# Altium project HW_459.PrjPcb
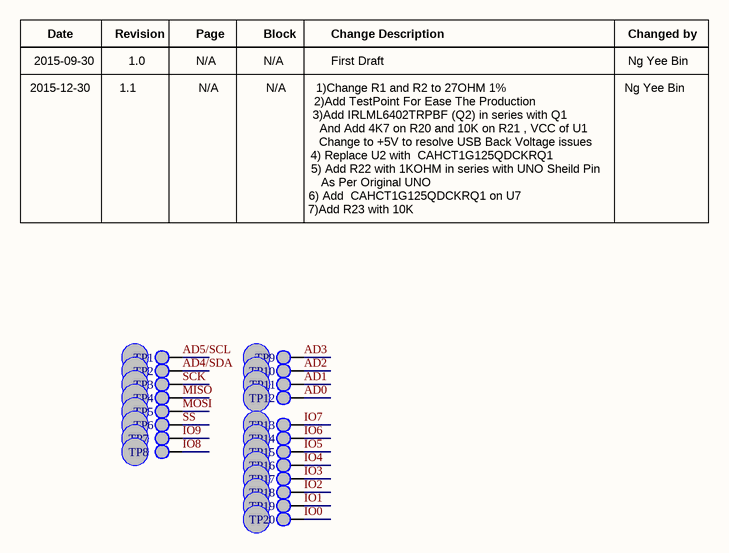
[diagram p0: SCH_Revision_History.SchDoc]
2 sheets, 108 parts. Net scope: global (net labels, ports and power ports of the same name join across sheets).
Board file: NERO.PcbDoc
Sheets:
  SCH_Revision_History.SchDoc
  nero.SchDoc

## Sheet SCH_Revision_History.SchDoc: FTDI Nero Schematic
size A4; CompanyName: Future Technology Devices International Ltd.; Organization: Future Technology Devices International Ltd.; Address1: 178 Paya Lebar Road,; Address2: #07-04/05; Address3: Singapore 409030; Address4: http://www.ftdichip.com; DocumentNumber: HW_459; Revision: 1.1; SheetNumber: 1; SheetTotal: 2; Title2: Revision History

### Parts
TP1  SMT_TP  [TP_SMT_1MM]  (value not drawn)  (no BOM)
TP2  SMT_TP  [TP_SMT_1MM]  (value not drawn)  (no BOM)
TP3  SMT_TP  [TP_SMT_1MM]  (value not drawn)  (no BOM)
TP4  SMT_TP  [TP_SMT_1MM]  (value not drawn)  (no BOM)
TP5  SMT_TP  [TP_SMT_1MM]  (value not drawn)  (no BOM)
TP6  SMT_TP  [TP_SMT_1MM]  (value not drawn)  (no BOM)
TP7  SMT_TP  [TP_SMT_1MM]  (value not drawn)  (no BOM)
TP8  SMT_TP  [TP_SMT_1MM]  (value not drawn)  (no BOM)
TP9  SMT_TP  [TP_SMT_1MM]  (value not drawn)  (no BOM)
TP10  SMT_TP  [TP_SMT_1MM]  (value not drawn)  (no BOM)
TP11  SMT_TP  [TP_SMT_1MM]  (value not drawn)  (no BOM)
TP12  SMT_TP  [TP_SMT_1MM]  (value not drawn)  (no BOM)
TP13  SMT_TP  [TP_SMT_1MM]  (value not drawn)  (no BOM)
TP14  SMT_TP  [TP_SMT_1MM]  (value not drawn)  (no BOM)
TP15  SMT_TP  [TP_SMT_1MM]  (value not drawn)  (no BOM)
TP16  SMT_TP  [TP_SMT_1MM]  (value not drawn)  (no BOM)
TP17  SMT_TP  [TP_SMT_1MM]  (value not drawn)  (no BOM)
TP18  SMT_TP  [TP_SMT_1MM]  (value not drawn)  (no BOM)
TP19  SMT_TP  [TP_SMT_1MM]  (value not drawn)  (no BOM)
TP20  SMT_TP  [TP_SMT_1MM]  (value not drawn)  (no BOM)

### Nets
AD0: TP12.TP
AD1: TP11.TP
AD2: TP10.TP
AD3: TP9.TP
AD4/SDA: TP2.TP
AD5/SCL: TP1.TP
IO0: TP20.TP
IO1: TP19.TP
IO2: TP18.TP
IO3: TP17.TP
IO4: TP16.TP
IO5: TP15.TP
IO6: TP14.TP
IO7: TP13.TP
IO8: TP8.TP
IO9: TP7.TP
MISO: TP4.TP
MOSI: TP5.TP
SCK: TP3.TP
SS: TP6.TP

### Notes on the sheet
- 2015-09-30
- Date
- Revision
- 1.0
- Page
- N/A
- Block
- Change Description
- First Draft
- Changed by
- Ng Yee Bin
- 2015-12-30
- 1.1
- 1)Change R1 and R2 to 27OHM 1%
- 2)Add TestPoint For Ease The Production
- 3)Add IRLML6402TRPBF (Q2) in series with Q1
- And Add 4K7 on R20 and 10K on R21 , VCC of U1
- As Per Original UNO
- 6) Add  CAHCT1G125QDCKRQ1 on U7
- 4) Replace U2 with  CAHCT1G125QDCKRQ1
- Change to +5V to resolve USB Back Voltage issues
- 5) Add R22 with 1KOHM in series with UNO Sheild Pin
- 7)Add R23 with 10K

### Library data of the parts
TP1-TP20 = TP_SMT_1mm

## Sheet nero.SchDoc: FTDI Nero Schematic
size A4; CompanyName: Future Technology Devices International Ltd.; Organization: Future Technology Devices International Ltd.; Address1: 178 Paya Lebar Road,; Address2: #07-04/05; Address3: Singapore 409030; Address4: http://www.ftdichip.com; DocumentNumber: HW_459; Revision: 1.1; SheetNumber: 2; SheetTotal: 2; Title2: Inspired by Arduino UNO R3
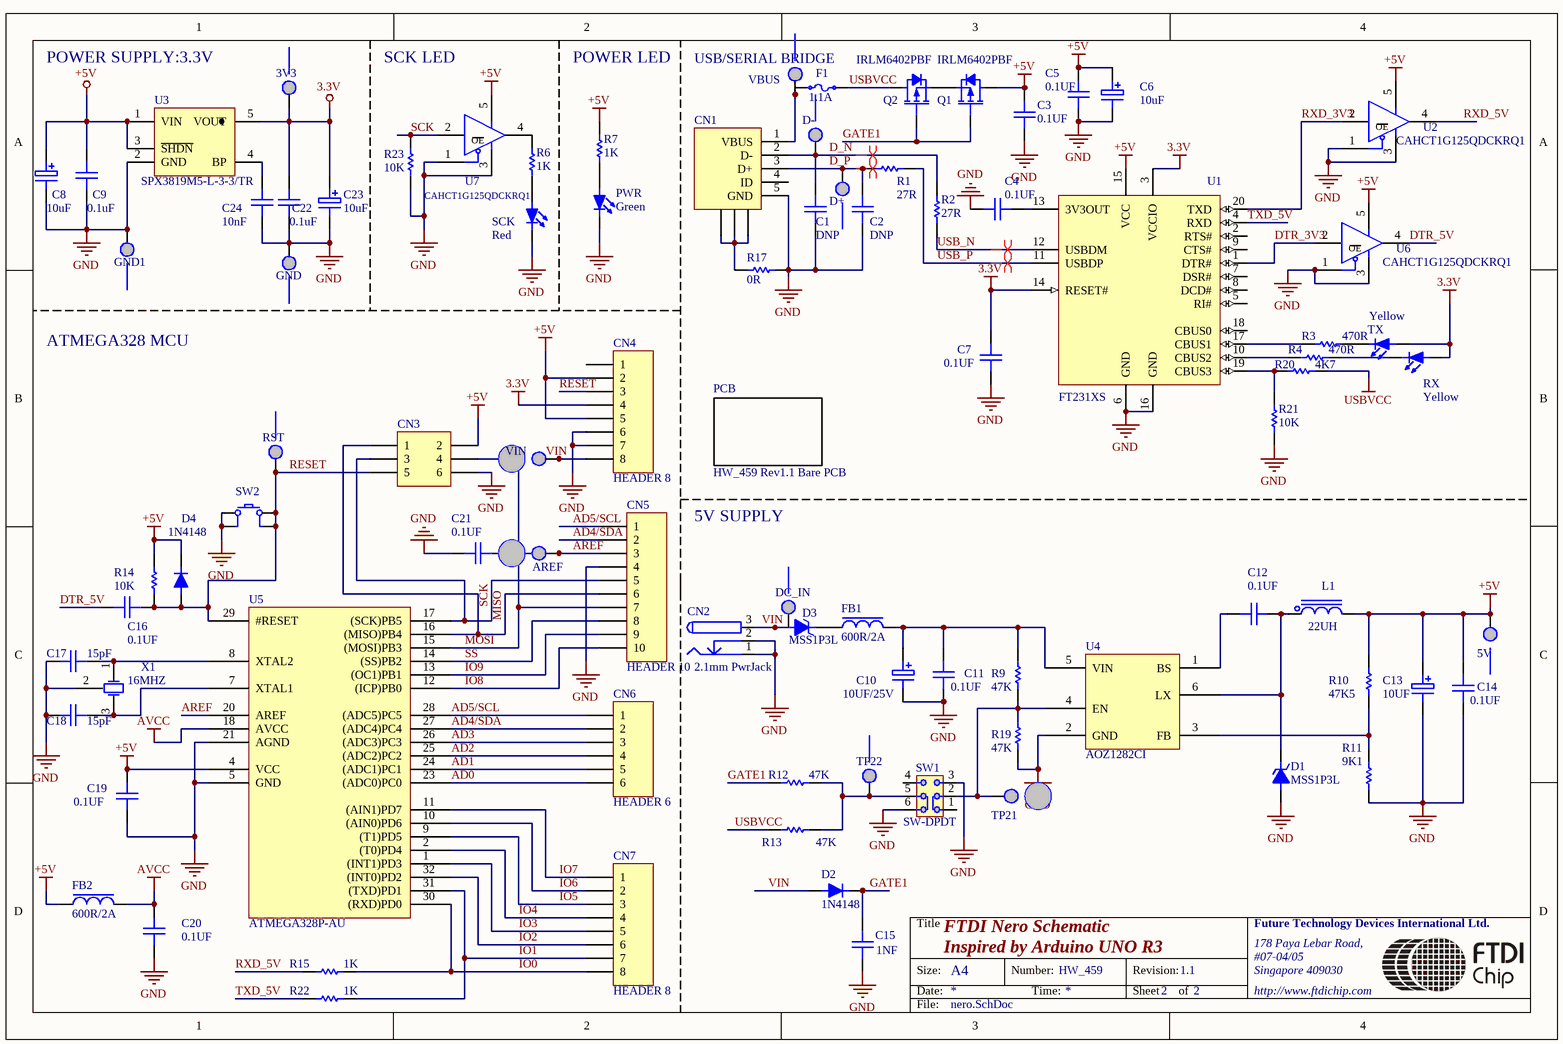
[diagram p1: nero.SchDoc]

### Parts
3V3  SMT_TP  [TP_SMT_1MM]  (value not drawn)  (no BOM)
5V  SMT_TP  [TP_SMT_1MM]  (value not drawn)  (no BOM)
AREF  SMT_TP  [TP_SMT_1MM]  (value not drawn)  (no BOM)
C1  DNP  [CAPC1608-0603]  (no BOM)
C2  DNP  [CAPC1608-0603]  (no BOM)
C3  0.1UF  [CAPC1608-0603]
C4  0.1UF  [CAPC1608-0603]
C5  0.1UF  [CAPC1608-0603]
C6  10uF  [CAPM-A-3216-18]
C7  0.1UF  [CAPC1608-0603]
C8  10uF  [CAPM-A-3216-18]
C9  0.1uF  [CAPC1608-0603]
C10  10UF/25V  [CAPM-B-3528-21]
C11  0.1UF  [CAPC1608-0603]
C12  0.1UF  [CAPC1608-0603]
C13  10UF  [CAPM-A-3216-18]
C14  0.1UF  [CAPC1608-0603]
C15  1NF  [CAPC1608-0603]
C16  0.1UF  [CAPC1608-0603]
C17  15pF  [CAPC1608-0603]
C18  15pF  [CAPC1608-0603]
C19  0.1UF  [CAPC1608-0603]
C20  0.1UF  [CAPC1608-0603]
C21  0.1UF  [CAPC1608-0603]
C22  0.1uF  [CAPC1608-0603]
C23  10uF  [CAPM-A-3216-18]
C24  10nF  [CAPC1608-0603]
CN1  CN USB  [CN_USB_MICRO_HOUSING]  (value not drawn)
CN2  2.1mm PwrJack  [CN_2.1mm Power Socket routed pins]
CN3  TC2030-IDC-FP  [CN_HDR2X3]  (value not drawn)
CN4  HEADER 8  [CN_HDR1X8]
CN5  HEADER 10  [CN_HDR1X10]
CN6  HEADER 6  [HDR1X6]
CN7  HEADER 8  [CN_HDR1X8]
D1  MSS1P3L  [DIODE_MSS1P3L]
D2  1N4148  [SOD-323]
D3  MSS1P3L  [DIODE_MSS1P3L]
D4  1N4148  [SOD-323]
D+  SMT_TP  [TP_SMT_1MM]  (value not drawn)  (no BOM)
D-  SMT_TP  [TP_SMT_1MM]  (value not drawn)  (no BOM)
DC_IN  SMT_TP  [TP_SMT_1MM]  (value not drawn)  (no BOM)
F1  1.1A  [Fuse_0ZCG Series]
FB1  600R/2A  [IND_C2012-0805]
FB2  600R/2A  [IND_C2012-0805]
GND  SMT_TP  [TP_SMT_1MM]  (value not drawn)  (no BOM)
GND1  SMT_TP  [TP_SMT_1MM]  (value not drawn)  (no BOM)
L1  22UH  [IND_NR6020]
PCB  HW_459 Rev1.1 Bare PCB
PWR  Green  [LEDC2012-0805]
Q1  IRLM6402PBF  [SOT23-3AL]
Q2  IRLM6402PBF  [SOT23-3AL]
R1  27R  [RESC1608-0603]
R2  27R  [RESC1608-0603]
R3  470R  [RESC1608-0603]
R4  470R  [RESC1608-0603]
R6  1K  [RESC1608-0603]
R7  1K  [RESC1608-0603]
R9  47K  [RESC1608-0603]
R10  47K5  [RESC1608-0603]
R11  9K1  [RESC1608-0603]
R12  47K  [RESC1608-0603]
R13  47K  [RESC1608-0603]
R14  10K  [RESC1608-0603]
R15  1K  [RESC1608-0603]
R17  0R  [RESC1608-0603]
R19  47K  [RESC1608-0603]
R20  4K7  [RESC1608-0603]
R21  10K  [RESC1608-0603]
R22  1K  [RESC1608-0603]
R23  10K  [RESC1608-0603]
RST  SMT_TP  [TP_SMT_1MM]  (value not drawn)  (no BOM)
RX  Yellow  [LEDC2012-0805]
SCK  Red  [LEDC2012-0805]
SW1  SW-DPDT  [SW_JS202011AQN]
SW2  SW_PB  [SW_PushButton]  (value not drawn)
TP21  SMT_TP  [TP_SMT_1MM]  (value not drawn)  (no BOM)
TP22  SMT_TP  [TP_SMT_1MM]  (value not drawn)  (no BOM)
TX  Yellow  [LEDC2012-0805]
U1  FT231XS  [SSOP20]
U2  CAHCT1G125QDCKRQ1  [SC70-5]
U3  SPX3819M5-L-3-3/TR  [SOT23-5AL]
U4  AOZ1282CI  [SOT23-6N]
U5  ATMEGA328P-AU  [TQFP80P900X900X160-32N]
U6  CAHCT1G125QDCKRQ1  [SC70-5]
U7  CAHCT1G125QDCKRQ1  [SC70-5]
VBUS  SMT_TP  [TP_SMT_1MM]  (value not drawn)  (no BOM)
VIN  SMT_TP  [TP_SMT_1MM]  (value not drawn)  (no BOM)
X1  16MHZ  [CRYSTAL_16MHZ]

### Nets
3.3V: 3V3.TP C7.1 C22.1 C23.1 CN4.4 RX.2(A) TX.2(A) U1.3(VCCIO) U1.14(RESET#) U3.5(VOUT)
+5V: 5V.TP C3.1 C5.1 C6.1 C8.1 C9.1 C13.1 C14.1 C19.1 CN3.2 CN4.2 CN4.5 D4.1(K) FB2.2 L1.2 Q1.3(D) R7.1 R10.2 R14.2 U1.15(VCC) U2.5(VCC) U3.1(VIN) U3.3(~{SHDN}) U5.4(VCC) U6.5(VCC) U7.5(VCC)
AVCC: C20.1 FB2.1 U5.18(AVCC)
GND: C1.2 C2.2 C3.2 C4.1 C5.2 C6.2 C7.2 C8.2 C9.2 C10.2 C11.2 C13.2 C14.2 C15.2 C17.1 C18.1 C19.2 C20.2 C21.1 C22.2 C23.2 C24.2 CN1.5(GND) CN2.1 CN2.2 CN3.6 CN4.6 CN4.7 CN5.4 D1.2(A) GND.TP GND1.TP PWR.1(K) R11.1 R17.2 R19.2 R21.1 R23.2 SCK.1(K) SW1.3 SW1.6 SW2.1 SW2.2 U1.6(GND) U1.16(GND) U2.1(~{OE}) U2.3(GND) U3.2(GND) U4.2(GND) U5.5(GND) U5.21(AGND) U6.1(~{OE}) U6.3(GND) U7.1(~{OE}) U7.3(GND) X1.2(GND)
USBVCC: F1.2 Q2.3(D) R13.1 R20.1
AD0: CN6.6 U5.23((ADC0)PC0)
AD1: CN6.5 U5.24((ADC1)PC1)
AD2: CN6.4 U5.25((ADC2)PC2)
AD3: CN6.3 U5.26((ADC3)PC3)
AD4/SDA: CN5.2 CN6.2 U5.27((ADC4)PC4)
AD5/SCL: CN5.1 CN6.1 U5.28((ADC5)PC5)
AREF: AREF.TP C21.2 CN5.3 U5.20(AREF)
D_N: C1.1 CN1.2(D-) D-.TP R2.2
D_P: C2.1 CN1.3(D+) D+.TP R1.1
DTR_3V3: U1.1(DTR#) U6.2(A)
DTR_5V: C16.1 U6.4(Y)
GATE1: C15.1 D2.1(K) Q1.1(G) Q2.1(G) R12.1
IO0: CN7.8 R15.2 U5.30((RXD)PD0)
IO1: CN7.7 R22.2 U5.31((TXD)PD1)
IO2: CN7.6 U5.32((INT0)PD2)
IO3: CN7.5 U5.1((INT1)PD3)
IO4: CN7.4 U5.2((T0)PD4)
IO5: CN7.3 U5.9((T1)PD5)
IO6: CN7.2 U5.10((AIN0)PD6)
IO7: CN7.1 U5.11((AIN1)PD7)
IO8: CN5.10 U5.12((ICP)PB0)
IO9: CN5.9 U5.13((OC1)PB1)
MISO: CN3.1 CN5.6 U5.16((MISO)PB4)
MOSI: CN3.4 CN5.7 U5.15((MOSI)PB3)
RESET: C16.2 CN3.5 CN4.3 D4.2(A) R14.1 RST.TP SW2.3 SW2.4 U5.29(#RESET)
RXD_3V3: U1.20(TXD) U2.2(A)
RXD_5V: R15.1 U2.4(Y)
SCK: CN3.3 CN5.5 R23.1 U5.17((SCK)PB5) U7.2(A)
SS: CN5.8 U5.14((SS)PB2)
TXD_5V: R22.1 U1.4(RXD)
USB_N: R2.1 U1.12(USBDM)
USB_P: R1.2 U1.11(USBDP)
VIN: CN2.3 CN4.8 D2.2(A) D3.2(A) DC_IN.TP VIN.TP
NetC4_2: C4.2 U1.13(3V3OUT)
NetC10_1: C10.1 C11.1 FB1.1 R9.1 U4.5(VIN)
NetC12_1: C12.1 U4.1(BS)
NetC12_2: C12.2 D1.1(K) L1.1 U4.6(LX)
NetC17_2: C17.2 U5.8(XTAL2) X1.1(OSC1)
NetC18_2: C18.2 U5.7(XTAL1) X1.3(OSC2)
NetC24_1: C24.1 U3.4(BP)
NetCN1_1: CN1.1(VBUS) F1.1 VBUS.TP
NetCN1_6: CN1.6(SHLD) CN1.7(SHLD) CN1.8(SHLD) R17.1
NetD3_1: D3.1(K) FB1.2
NetPWR_2: PWR.2(A) R7.2
NetQ1_2: Q1.2(S) Q2.2(S)
NetR3_1: R3.1 U1.17(CBUS1)
NetR3_2: R3.2 TX.1(K)
NetR4_1: R4.1 U1.10(CBUS2)
NetR4_2: R4.2 RX.1(K)
NetR6_1: R6.1 U7.4(Y)
NetR6_2: R6.2 SCK.2(A)
NetR9_2: R9.2 R19.1 SW1.2 TP21.TP U4.4(EN)
NetR10_1: R10.1 R11.2 U4.3(FB)
NetR12_2: R12.2 R13.2 SW1.5 TP22.TP
NetR20_2: R20.2 R21.2 U1.19(CBUS3)

Not connected (* = marked no-connect by the designer): CN1 4(ID); CN4 1; SW1 1 4; U1 2(RTS#) 5(RI#) 7(DSR#) 8(DCD#) 9(CTS#) 18(CBUS0)

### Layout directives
differential pair: D_N, D_P, USB_N, USB_P

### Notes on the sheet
- POWER SUPPLY:3.3V
- SCK LED
- POWER LED
- USB/SERIAL BRIDGE
- ATMEGA328 MCU
- 5V SUPPLY

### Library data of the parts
3V3 5V AREF D+ D- DC_IN GND GND1 RST TP21 TP22 VBUS VIN = TP_SMT_1mm
C1 C2 = CAP_SEMI: Capacitor bipolar
C3-C5 C7 C9 C11 C12 C14 C16 C19 C20 = CAP_SEMI: Capacitor bipolar; Manufacturer: Samsung Electro-Mechanics America, Inc.; ManufacturerPartNo: CL10B104KB8SFNC; Note: CAP CERAMIC .1UF 50V X7R 0603
C6 C8 C13 C23 = CAP_POL: Polarized Capacitor; Manufacturer: AVX Corporation; ManufacturerPartNo: TAJA106M010RNJ; Note: CAP TANT LOESR 10.0UF 10V 20% SMD 1206
C10 = CAP_POL: Polarized Capacitor; Manufacturer: AVX Corporation; ManufacturerPartNo: TAJB106M025RNJ; Note: CAP TANT 10UF 25V 20% 1210
C15 = CAP_SEMI: Capacitor bipolar; Manufacturer: Samsung Electro-Mechanics America, Inc.; ManufacturerPartNo: CL10B102KB8SFNC; Note: CAP 1000PF 50V CERAMIC X7R 0603
C17 C18 = CAP_SEMI: Capacitor bipolar; Manufacturer: Samsung Electro-Mechanics America, Inc.; ManufacturerPartNo: CL10C150JB8NNNC; Note: CAP CER 15PF 50V 5% NPO 0603
C21 C22 = CAP_SEMI: Capacitor bipolar; ManufacturerPartNo: CL10B104KB8SFNC; Manufacturer: Samsung Electro-Mechanics America, Inc.; Note: CAP CERAMIC .1UF 50V X7R 0603
C24 = CAP_SEMI: Capacitor bipolar; Manufacturer: Samsung Electro-Mechanics America, Inc.; ManufacturerPartNo: CL10B103MB8NCNC; Note: CAP CER 10000PF 50V X7R 0603
CN1 = CN_USB_MINI_B: Mini USB connector; SMD; Manufacturer: E-CONN ELECTRONIC(SU-ZHOU) CO., LTD; ManufacturerPartNo: MIC5-5BF1-KNM1-23; Note: MICRO USB B REC. (HOUSEING HOLE)
CN2 = CN_Power Jack: Low Voltage Power Supply Connector; Manufacturer: CUI Inc; ManufacturerPartNo: PJ-002A; Note: CONN POWER JACK 2.1MM
CN3 = CN_HEADER 2x3: ISP Connector, 6-Pin, Dual row, pitch 0.05"; Tag-Connect; TC2030-IDC-FP; Manufacturer: Sullins Connector Solutions; ManufacturerPartNo: PBC03DAAN; Note: CONN HEADER .100 DUAL STR 6POS
CN4 CN7 = CN_HEADER 8: Header, 8-Pin; Manufacturer: JunJia Electronics Technology; ManufacturerPartNo: FAS1851-0801A03XABXA; Note: Connector Receptacle 8 Position 0.100" (2.54mm) Tin Through Hole
CN5 = CN_HEADER 10: Header, 10-Pin; Manufacturer: JunJia Electronics Technology; ManufacturerPartNo: FAS1851-1001A03XABXA; Note: Connector Receptacle 10 Position 0.100" (2.54mm) Tin Through Hole
CN6 = CN_HEADER 6: Header, 6-Pin; Manufacturer: JunJia Electronics Technology; ManufacturerPartNo: FAS1851-0601A03XABXA; Note: Connector Receptacle 6 Position 0.100" (2.54mm) Tin Through Hole
D1 D3 = D_ZENER: Zener Diode; Manufacturer: VISHAY SEMICONDUCTOR; Note: DIODE SCHOTTKY 30V 1A MICROSMP
D2 D4 = D_UNI: DIODE SWITCH 75V 200MW SOD323; Manufacturer: Diodes Inc; ManufacturerPartNo: 1N4148WS-7-F
F1 = FUSE 2: Fuse; Manufacturer: Bel Fuse Inc; ManufacturerPartNo: 0ZCG0110AF2C; Note: PTC RESTTBLE 1.10A 16V CHIP 1812
FB1 FB2 = FERRITE_BEAD: Chip Ferrite Bead 0805; Manufacturer: TDK Corporation; ManufacturerPartNo: MPZ2012S601A; Note: FERRITE CHIP 600 OHM 2A 0805
L1 = IND_POWER: Magnetic-Core Inductor; Manufacturer: TAIYO YUDEN; ManufacturerPartNo: NR6028T220M; Note: IND 22UH 1.4A +-20% 6X6X2.8MM
PCB = PCB
PWR = D_LED: Typical LED diode; Manufacturer: Lite-On Inc; ManufacturerPartNo: LTST-C170GKT; Note: LED GREEN CLEAR 0805 SMD
Q1 Q2 = T_MOSFET-P: P-Channel MOSFET; SOT-23; Manufacturer: International Rectifier; ManufacturerPartNo: IRLML6402TRPBF; Note: MOSFET P-CH 20V 3.7A SOT-23
R1 R2 = RES1: Resistor; Manufacturer: UniOhm; ManufacturerPartNo: 0603WGF0270; Note: RES 27R OHM 1/16W 1% 0603 SMD
R3 R4 = RES1: Resistor; Manufacturer: UniOhm; ManufacturerPartNo: 0603WGJ0471; Note: RES 470 OHM 5% 1/16W 0603 SMD
R6 R7 R15 R22 = RES1: Resistor; Manufacturer: UniOhm; ManufacturerPartNo: 0603WGJ0102; Note: RES 1K OHM 1/16W 5% 0603 SMD
R9 R12 R13 R19 = RES1: Resistor; Manufacturer: UniOhm; ManufacturerPartNo: 0603WGJ0473; Note: RES 47K OHM 1/16W 5% 0603 SMD
R10 = RES1: Resistor; Manufacturer: UniOhm; ManufacturerPartNo: 0603WGF4752; Note: RES 47K5 OHM 1/16W 1% 0603 SMD
R11 = RES1: Resistor; Manufacturer: UniOhm; ManufacturerPartNo: 0603WGF0912; Note: RES 9K1 OHM 1% 1/16W 0603 SMD
R14 R21 R23 = RES1: Resistor; Manufacturer: UniOhm; ManufacturerPartNo: 0603WGF0103; Note: RES 10K OHM 1/16W 1% 0603 SMD
R17 = RES1: Resistor; Manufacturer: UniOhm; ManufacturerPartNo: 0603WAF0000XXX; Note: RES 0 OHM 1/16W 0603 SMD
R20 = RES1: Resistor; Manufacturer: UniOhm; ManufacturerPartNo: 0603WGF0472; Note: RES 4K7 OHM 1% 1/16W 0603 SMD
RX TX = D_LED: Typical LED diode; Manufacturer: Lite-On Inc; ManufacturerPartNo: LTST-C170YKT; Note: LED YELLOW CLEAR 0805 SMD
SCK = D_LED: Typical LED diode; Manufacturer: Chicago Miniature Lighting, LLC; ManufacturerPartNo: 7012X1; Note: LED RED CLEAR 0805 SMD
SW1 = SW-SPDT: SPDT Switch; Manufacturer: C&K Components; ManufacturerPartNo: JS202011AQN; Note: SWITCH SLIDE DPDT 300MA 6V
SW2 = SW_PB_4PIN: Push button momentary switch; Manufacturer: TE Connectivity Alcoswitch Switches; ManufacturerPartNo: 1825910-6; Note: SWITCH TACTILE SPST-NO 0.05A 24V
U1 = IC_FT231XS: FT231XS-SSOP-20; ManufacturerPartNo: FT231XS-R; Manufacturer: FTDI chip; Note: IC USB SERIAL FULL UART 20SSOP
U2 U6 U7 = IC_SN74LVC1G125DBVR: IC BUS BUFF GATE 3ST SGL SC70-5; Manufacturer: Texas Instruments; Note: Do not change to other vendor
U3 = IC_AIC1733: 500mA, Low Dropout Linear Regulator  with Shutdown; Manufacturer: Exar Corporation; Note: IC REG LDO 3.3V 0.5A SOT23-5
U4 = AOZ1282CI: IC REG BUCK ADJ 1.2A SOT23-6; Manufacturer: ALPHA&OMEGA SEMICONDUCTOR
U5 = IC_ATMEGA328P-AU: IC MCU 8BIT 32KB FLASH 32TQFP; Manufacturer: ATMEL
X1 = XTAL: Crystal Oscillator; Manufacturer: Murata Electronic; ManufacturerPartNo: CSTCE16M0V53-R0; Note: CER RESONATOR 16.0MHZ SMD

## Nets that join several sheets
AD0: SCH_Revision_History (TP12.TP), nero (CN6.6 U5.23)
AD1: SCH_Revision_History (TP11.TP), nero (CN6.5 U5.24)
AD2: SCH_Revision_History (TP10.TP), nero (CN6.4 U5.25)
AD3: SCH_Revision_History (TP9.TP), nero (CN6.3 U5.26)
AD4/SDA: SCH_Revision_History (TP2.TP), nero (CN5.2 CN6.2 U5.27)
AD5/SCL: SCH_Revision_History (TP1.TP), nero (CN5.1 CN6.1 U5.28)
IO0: SCH_Revision_History (TP20.TP), nero (CN7.8 R15.2 U5.30)
IO1: SCH_Revision_History (TP19.TP), nero (CN7.7 R22.2 U5.31)
IO2: SCH_Revision_History (TP18.TP), nero (CN7.6 U5.32)
IO3: SCH_Revision_History (TP17.TP), nero (CN7.5 U5.1)
IO4: SCH_Revision_History (TP16.TP), nero (CN7.4 U5.2)
IO5: SCH_Revision_History (TP15.TP), nero (CN7.3 U5.9)
IO6: SCH_Revision_History (TP14.TP), nero (CN7.2 U5.10)
IO7: SCH_Revision_History (TP13.TP), nero (CN7.1 U5.11)
IO8: SCH_Revision_History (TP8.TP), nero (CN5.10 U5.12)
IO9: SCH_Revision_History (TP7.TP), nero (CN5.9 U5.13)
MISO: SCH_Revision_History (TP4.TP), nero (CN3.1 CN5.6 U5.16)
MOSI: SCH_Revision_History (TP5.TP), nero (CN3.4 CN5.7 U5.15)
SCK: SCH_Revision_History (TP3.TP), nero (5 pins)
SS: SCH_Revision_History (TP6.TP), nero (CN5.8 U5.14)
